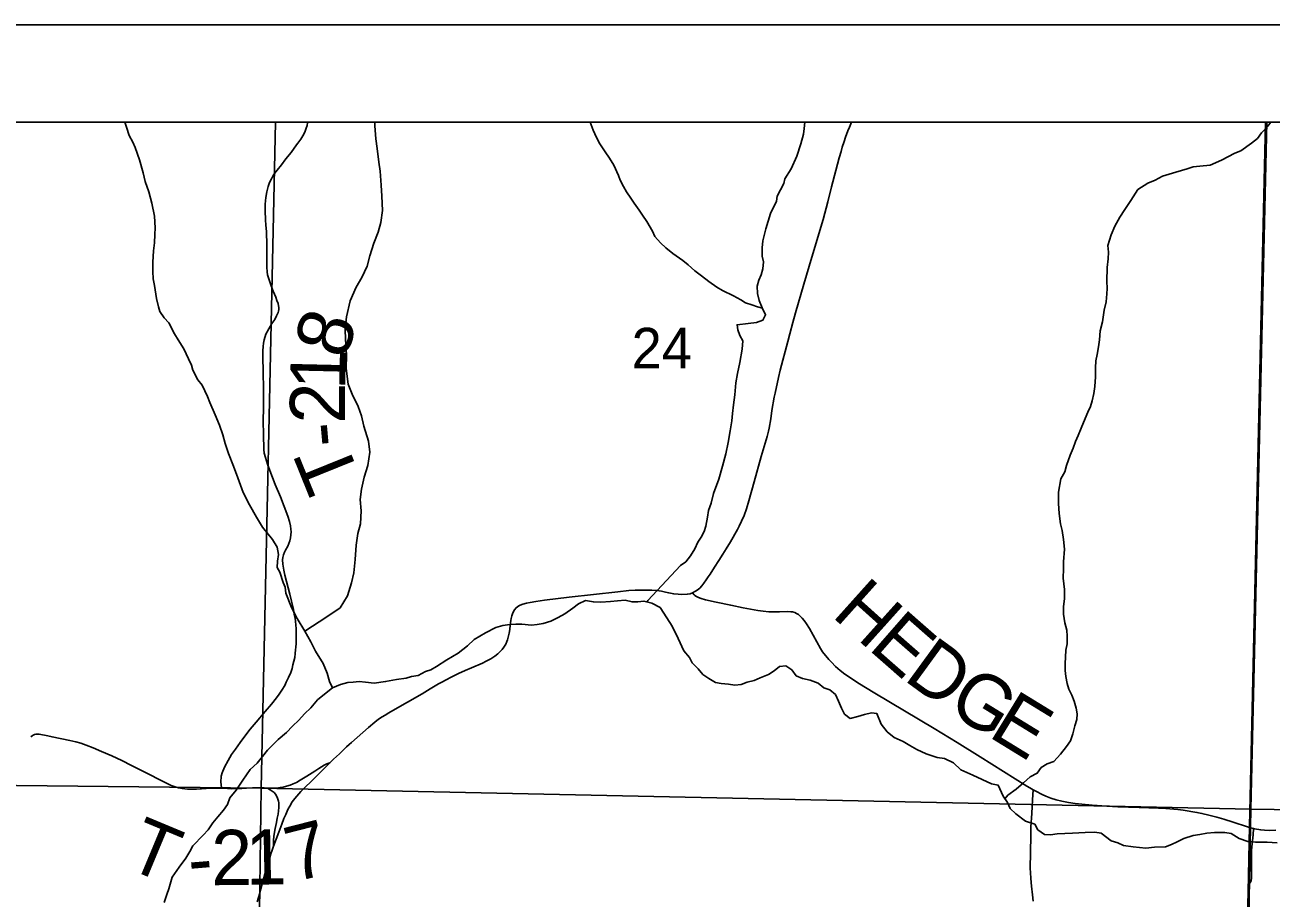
# Model space of a CAD drawing. Extents: x 0 to 34, y 0 to 22.
# Drawn here: x 20.014 to 21.298, y 19.601 to 20.5 of the extents above; entities that cross this region are included whole.
import ezdxf

# ---------------------------------------------------------------- set-up
doc = ezdxf.new("R2010")
doc.units = 0
for name, color, linetype in [('GM_X_Corporation', 7, 'Continuous'), ('GM_X_County_Road', 7, 'Continuous'), ('GM_X_Minor_River', 7, 'Continuous'), ('GM_X_Section_Text', 7, 'Continuous'), ('GM_X_Township_Road', 7, 'Continuous'), ('GM_X_Township_Road_Text', 7, 'Continuous'), ('SH_Data', 7, 'Continuous')]:
    doc.layers.add(name, color=color, linetype=linetype)

msp = doc.modelspace()

# ---------------------------------------------------------------- linework, layer by layer
at = {"layer": 'GM_X_Corporation'}
for points in [[(21.2921, 20.4), (18.6, 20.4), (18.6, 19.2331), (18.9898, 19.2261), (20.065, 19.208), (20.254, 19.2058), (20.8916, 19.1966), (21.2652, 19.1913), (21.273, 19.5535), (21.2742, 19.6071), (21.2757, 19.6748)], [(20.2723, 20.4), (19.267, 20.4), (19.2491, 19.7249), (20.2574, 19.7138)], [(21.2934, 20.4), (20.2723, 20.4), (20.2574, 19.7138), (21.2769, 19.6922)], [(25.4, 19.0068), (25.4, 20.4), (21.2921, 20.4), (21.2757, 19.6748), (21.2742, 19.6071), (21.273, 19.5535), (21.2652, 19.1913), (21.5297, 19.1865), (21.7744, 19.1817), (21.8956, 19.1793), (22.6423, 19.1645), (23.3329, 19.1508), (23.5499, 19.1465), (23.786, 19.1434), (24.169, 19.1418), (24.3186, 19.1409), (24.3186, 19.0261), (24.5766, 19.0222)], [(22.3096, 20.4), (21.2934, 20.4), (21.2769, 19.6922), (22.2928, 19.6778)], [(19.2491, 19.7249), (20.2574, 19.7138), (20.2437, 18.6978), (19.241, 18.7106), (19.2491, 19.7204)], [(21.2769, 19.6922), (21.2582, 18.6819), (20.2437, 18.6978), (20.2574, 19.7138)], [(22.2928, 19.6778), (22.2749, 18.6656), (21.2582, 18.6819), (21.2769, 19.6922)]]:
    msp.add_lwpolyline(points, close=True, dxfattribs=at)
at = {"layer": 'GM_X_County_Road'}
for points in [[(20.2997, 19.7119), (20.3028, 19.715), (20.3088, 19.721), (20.3185, 19.7304), (20.3252, 19.7371), (20.3283, 19.7401), (20.3321, 19.744), (20.338, 19.7494), (20.3453, 19.7565), (20.348, 19.7589), (20.3505, 19.7611), (20.368, 19.7763), (20.3744, 19.7818), (20.3784, 19.7849), (20.3821, 19.7874), (20.3851, 19.7893), (20.3891, 19.7916), (20.393, 19.7939), (20.4232, 19.8112), (20.4316, 19.8162), (20.4402, 19.8213), (20.4443, 19.8235), (20.4474, 19.8252), (20.454, 19.8286), (20.4607, 19.8319), (20.4676, 19.835), (20.4741, 19.8378), (20.4855, 19.8428), (20.4894, 19.8448), (20.4939, 19.8473), (20.4981, 19.85), (20.5014, 19.8524), (20.5038, 19.8546), (20.5059, 19.8568), (20.5076, 19.8591), (20.5094, 19.8621), (20.5107, 19.8649), (20.5114, 19.8667), (20.5121, 19.8696), (20.5129, 19.8736), (20.5135, 19.8773), (20.5141, 19.882), (20.5147, 19.8867), (20.515, 19.8886), (20.5156, 19.8913), (20.5163, 19.8935), (20.517, 19.8953), (20.5183, 19.8976), (20.52, 19.8997), (20.5215, 19.9008), (20.5229, 19.9018), (20.5244, 19.9025), (20.5272, 19.9036), (20.5309, 19.9046), (20.5346, 19.9053), (20.5404, 19.9062), (20.5494, 19.9075), (20.5747, 19.9107), (20.6248, 19.9163), (20.6362, 19.9174), (20.6427, 19.9178), (20.6493, 19.918), (20.6599, 19.9179), (20.6652, 19.9174), (20.6699, 19.9167), (20.6741, 19.9158), (20.6773, 19.9151), (20.6825, 19.9141), (20.6871, 19.9136), (20.6908, 19.9133), (20.6965, 19.9136), (20.6994, 19.9142), (20.7019, 19.9152), (20.7042, 19.9164), (20.7057, 19.9173), (20.7079, 19.9188), (20.7095, 19.9201), (20.7115, 19.9224), (20.7136, 19.925), (20.7159, 19.9284), (20.718, 19.9316), (20.7199, 19.9344), (20.7245, 19.9415), (20.729, 19.9484), (20.7331, 19.9548), (20.7365, 19.9603), (20.741, 19.9676), (20.7482, 19.9803), (20.75, 19.9839), (20.7524, 19.989), (20.7549, 19.9949), (20.7573, 20.0017), (20.7598, 20.01), (20.7652, 20.0296), (20.7727, 20.0555), (20.7767, 20.0693), (20.7787, 20.076), (20.7802, 20.0818), (20.7809, 20.0848), (20.7825, 20.0944), (20.7837, 20.103), (20.7861, 20.1167), (20.7869, 20.1208), (20.7904, 20.1368), (20.7922, 20.1444), (20.7999, 20.1741), (20.8021, 20.1818), (20.8052, 20.1934), (20.808, 20.2035), (20.8165, 20.233), (20.822, 20.2516), (20.8321, 20.2847), (20.8363, 20.2997), (20.8412, 20.3177), (20.8452, 20.3332), (20.8496, 20.35), (20.8531, 20.363), (20.8549, 20.3697), (20.8562, 20.374), (20.8581, 20.38), (20.8596, 20.3845), (20.862, 20.3911), (20.8635, 20.3947), (20.8656, 20.4)], [(20.2533, 19.5969), (20.2548, 19.6015), (20.256, 19.606), (20.2572, 19.6104), (20.2596, 19.6193), (20.2611, 19.6253), (20.2625, 19.6302), (20.2638, 19.6351), (20.2663, 19.6426), (20.2675, 19.6464), (20.2689, 19.6501), (20.2703, 19.6541), (20.2757, 19.6685), (20.2788, 19.677), (20.2809, 19.6826), (20.2828, 19.687), (20.2844, 19.6904), (20.2854, 19.6926), (20.2869, 19.6956), (20.2895, 19.7), (20.2922, 19.7032), (20.2982, 19.7104), (20.2997, 19.7119)]]:
    msp.add_lwpolyline(points, dxfattribs=at)
at = {"layer": 'GM_X_Minor_River'}
for points in [[(20.3308, 19.8173), (20.328, 19.8237), (20.3253, 19.8325), (20.3213, 19.8423), (20.3136, 19.8551), (20.3085, 19.8646), (20.3023, 19.8755), (20.2945, 19.8887), (20.2887, 19.9), (20.2828, 19.9148), (20.2823, 19.9209), (20.28, 19.9258), (20.2768, 19.9364), (20.2741, 19.9413), (20.2744, 19.9478), (20.2754, 19.9547), (20.2741, 19.9623), (20.2691, 19.9702), (20.2587, 19.9826), (20.2525, 19.9931), (20.2455, 20.0056), (20.2389, 20.0184), (20.2333, 20.0336), (20.229, 20.0457), (20.2239, 20.0586), (20.2203, 20.0688), (20.2179, 20.0779), (20.2144, 20.0877), (20.2101, 20.0983), (20.2046, 20.1112), (20.2022, 20.1172), (20.1967, 20.129), (20.1921, 20.1346), (20.1871, 20.1444), (20.1858, 20.1497), (20.1827, 20.1562), (20.1777, 20.1664), (20.1718, 20.1758), (20.1683, 20.1818), (20.1625, 20.1932), (20.1575, 20.1984), (20.1532, 20.2048), (20.1517, 20.2097), (20.1496, 20.2181), (20.1475, 20.2318), (20.1463, 20.2386), (20.1458, 20.2462), (20.1457, 20.2557), (20.1466, 20.2675), (20.1477, 20.2755), (20.1479, 20.2843), (20.1482, 20.2911), (20.1476, 20.3029), (20.1448, 20.3166), (20.1416, 20.328), (20.138, 20.3389), (20.136, 20.3477), (20.132, 20.3609), (20.1277, 20.3738), (20.1253, 20.3791), (20.1214, 20.3863), (20.1187, 20.3946), (20.117, 20.4)], [(20.3023, 19.8755), (20.3251, 19.8905), (20.3388, 19.8996), (20.3464, 19.9122), (20.3506, 19.9255), (20.3529, 19.9357), (20.3544, 19.9494), (20.3555, 19.9642), (20.3571, 19.9764), (20.3597, 19.9862), (20.3605, 19.9995), (20.3593, 20.0113), (20.3608, 20.0219), (20.3635, 20.0341), (20.3673, 20.0462), (20.3695, 20.0599), (20.368, 20.0713), (20.3634, 20.0869), (20.3607, 20.0975), (20.3573, 20.107), (20.3512, 20.1199), (20.347, 20.1302), (20.345, 20.1461), (20.3454, 20.1602), (20.3443, 20.1765), (20.3439, 20.1864), (20.3454, 20.1993), (20.3492, 20.216), (20.3552, 20.23), (20.361, 20.2399), (20.3667, 20.2517), (20.3693, 20.2623), (20.3735, 20.2752), (20.3781, 20.2866), (20.3807, 20.2965), (20.3826, 20.309), (20.3818, 20.3238), (20.3811, 20.3349), (20.3799, 20.3493), (20.3787, 20.3588), (20.3768, 20.3728), (20.3757, 20.3827), (20.3745, 20.396), (20.3744, 20.4)], [(20.5965, 20.4), (20.5995, 20.3915), (20.603, 20.3839), (20.6065, 20.3775), (20.612, 20.3692), (20.6162, 20.3628), (20.6209, 20.3557), (20.6256, 20.3451), (20.6272, 20.3401), (20.6307, 20.3337), (20.6338, 20.3281), (20.6384, 20.3217), (20.6419, 20.3164), (20.6469, 20.3092), (20.6504, 20.304), (20.6547, 20.2975), (20.6605, 20.2877), (20.6632, 20.2821), (20.669, 20.2757), (20.6744, 20.2704), (20.6816, 20.2645), (20.692, 20.2574), (20.6973, 20.2529), (20.7042, 20.2469), (20.7111, 20.2417), (20.7188, 20.2357), (20.7268, 20.2301), (20.7326, 20.2264), (20.744, 20.2209), (20.7516, 20.2168), (20.7566, 20.2138), (20.7631, 20.2116), (20.7688, 20.2098), (20.7739, 20.2083)], [(20.6551, 19.9057), (20.6557, 19.9072), (20.6894, 19.9433), (20.695, 19.9472), (20.6998, 19.9534), (20.7043, 19.9603), (20.7072, 19.9672), (20.7109, 19.9726), (20.7138, 19.9783), (20.7157, 19.9837), (20.7174, 19.9929), (20.7184, 20.0001), (20.721, 20.0074), (20.7235, 20.0173), (20.729, 20.0322), (20.7329, 20.0456), (20.7361, 20.0582), (20.7386, 20.0701), (20.7407, 20.0819), (20.7425, 20.0922), (20.7431, 20.0998), (20.7441, 20.1086), (20.7455, 20.1189), (20.7464, 20.1315), (20.7482, 20.141), (20.7507, 20.1525), (20.7531, 20.1662), (20.7538, 20.1746), (20.7506, 20.1802), (20.7487, 20.1859), (20.7478, 20.1912), (20.7592, 20.1926), (20.7679, 20.1934), (20.7743, 20.1958), (20.7772, 20.2016), (20.7737, 20.2088), (20.7706, 20.2163), (20.7689, 20.2235), (20.7685, 20.2311), (20.7703, 20.2373), (20.7725, 20.2426), (20.7743, 20.2487), (20.7749, 20.256), (20.7737, 20.2617), (20.7736, 20.2704), (20.7742, 20.2777), (20.7774, 20.2899), (20.7821, 20.3059), (20.7884, 20.3186), (20.7891, 20.3236), (20.7961, 20.3366), (20.7968, 20.3416), (20.8034, 20.3519), (20.8093, 20.365), (20.8136, 20.3776), (20.8161, 20.3875), (20.8168, 20.3932), (20.8175, 20.3997), (20.8175, 20.4)], [(21.0236, 19.7031), (21.0268, 19.7068), (21.0354, 19.713), (21.0428, 19.7196), (21.0496, 19.7258), (21.0571, 19.7293), (21.0612, 19.7351), (21.0672, 19.739), (21.074, 19.7414), (21.081, 19.7491), (21.087, 19.7568), (21.0911, 19.7626), (21.0936, 19.7698), (21.0958, 19.7782), (21.0979, 19.7848), (21.0982, 19.7905), (21.097, 19.7965), (21.095, 19.8037), (21.0926, 19.8098), (21.0895, 19.8158), (21.0879, 19.8219), (21.0863, 19.8291), (21.0858, 19.8352), (21.0857, 19.8424), (21.086, 19.8489), (21.0863, 19.8561), (21.0877, 19.8626), (21.088, 19.8706), (21.0875, 19.8767), (21.0855, 19.8843), (21.0839, 19.893), (21.0841, 19.901), (21.0851, 19.909), (21.085, 19.9185), (21.0837, 19.9303), (21.0839, 19.9398), (21.0842, 19.9471), (21.0851, 19.96), (21.0839, 19.9699), (21.0826, 19.9794), (21.081, 19.9862), (21.0797, 19.9968), (21.0788, 20.0071), (21.079, 20.0189), (21.0814, 20.0327), (21.0855, 20.0396), (21.0873, 20.0464), (21.0909, 20.0568), (21.0939, 20.0641), (21.0964, 20.0709), (21.099, 20.0771), (21.1023, 20.0847), (21.1063, 20.0947), (21.1092, 20.1012), (21.1118, 20.107), (21.1136, 20.1127), (21.1154, 20.1203), (21.1164, 20.1276), (21.117, 20.1375), (21.1169, 20.147), (21.1175, 20.1539), (21.1186, 20.1607), (21.12, 20.1684), (21.121, 20.1756), (21.122, 20.1851), (21.1241, 20.1943), (21.1259, 20.2061), (21.128, 20.2149), (21.1286, 20.2229), (21.1289, 20.2286), (21.1288, 20.2362), (21.129, 20.2503), (21.13, 20.2591), (21.1303, 20.2659), (21.1298, 20.2728), (21.133, 20.2839), (21.1371, 20.2927), (21.1422, 20.3019), (21.1471, 20.31), (21.1534, 20.3192), (21.1608, 20.3304), (21.1709, 20.337), (21.1784, 20.3401), (21.1859, 20.3441), (21.1999, 20.3485), (21.2116, 20.3517), (21.2176, 20.3537), (21.2244, 20.3545), (21.235, 20.3555), (21.247, 20.3606), (21.2606, 20.368), (21.2666, 20.3704), (21.2778, 20.3782), (21.2838, 20.3829), (21.2879, 20.389), (21.2946, 20.3956), (21.2976, 20.4)], [(20.2027, 19.6712), (20.2075, 19.6781), (20.2127, 19.6846), (20.2187, 19.6912), (20.2227, 19.697), (20.2253, 19.7039), (20.2316, 19.7119), (20.2387, 19.7223), (20.2461, 19.7331), (20.2532, 19.7397), (20.2587, 19.7466), (20.2639, 19.7531), (20.2751, 19.764), (20.2834, 19.7713), (20.2897, 19.7779), (20.2961, 19.7841), (20.302, 19.7906), (20.3087, 19.7968), (20.3154, 19.8049), (20.3244, 19.8123), (20.3308, 19.8173), (20.3391, 19.8209), (20.3466, 19.8229), (20.3523, 19.8233), (20.3583, 19.8238), (20.3648, 19.8232), (20.3739, 19.8221), (20.3856, 19.8238), (20.3969, 19.8259), (20.4067, 19.8272), (20.4124, 19.8288), (20.4192, 19.8301), (20.4267, 19.834), (20.4323, 19.836), (20.438, 19.8391), (20.4489, 19.8461), (20.4605, 19.8531), (20.4702, 19.8605), (20.4769, 19.8671), (20.4826, 19.8706), (20.4886, 19.8741), (20.4991, 19.8796), (20.5066, 19.8816), (20.5138, 19.8825), (20.5199, 19.8829), (20.5259, 19.8827), (20.5358, 19.882), (20.5418, 19.8825), (20.5479, 19.8834), (20.5558, 19.8858), (20.5633, 19.8897), (20.5704, 19.8936), (20.5787, 19.8994), (20.5843, 19.9037), (20.5915, 19.9072), (20.5998, 19.9058), (20.6074, 19.9056), (20.6172, 19.9061), (20.6244, 19.907), (20.6323, 19.9075), (20.6396, 19.9057), (20.6456, 19.9058), (20.6517, 19.9066), (20.66, 19.9045), (20.6684, 19.9), (20.6754, 19.8895), (20.6808, 19.8808), (20.6871, 19.868), (20.6929, 19.8555), (20.6987, 19.8487), (20.7014, 19.843), (20.7076, 19.8367), (20.7126, 19.831), (20.7187, 19.8269), (20.7256, 19.8229), (20.7313, 19.8218), (20.7389, 19.8212), (20.7453, 19.8201), (20.7521, 19.8206), (20.7581, 19.823), (20.7653, 19.825), (20.7717, 19.8277), (20.78, 19.8309), (20.786, 19.8348), (20.7916, 19.8391), (20.798, 19.8399), (20.8041, 19.8358), (20.8088, 19.8298), (20.8152, 19.8269), (20.8232, 19.8251), (20.8312, 19.8222), (20.8373, 19.8173), (20.8434, 19.8151), (20.8492, 19.8103), (20.8523, 19.8035), (20.8554, 19.7963), (20.8586, 19.7902), (20.8643, 19.7858), (20.8722, 19.7878), (20.879, 19.7898), (20.8862, 19.7914)], [(20.8862, 19.7914), (20.8919, 19.7907), (20.8962, 19.7798), (20.9024, 19.7719), (20.9096, 19.7663), (20.9188, 19.7619), (20.9257, 19.7578), (20.9329, 19.7537), (20.9425, 19.7493), (20.9539, 19.7456), (20.9615, 19.7446), (20.9706, 19.7402), (20.9783, 19.7327), (20.9905, 19.7272), (21.0099, 19.7183), (21.0168, 19.7169), (21.0219, 19.7056), (21.0265, 19.6992), (21.0292, 19.6931), (21.035, 19.6875), (21.0449, 19.68), (21.0545, 19.6768), (21.0576, 19.6711), (21.0645, 19.6663), (21.0705, 19.666), (21.0777, 19.6668), (21.0932, 19.6675), (21.1064, 19.6684), (21.1163, 19.6686), (21.1227, 19.6675), (21.1331, 19.6597), (21.1399, 19.6575), (21.146, 19.6549), (21.1559, 19.6536), (21.1688, 19.6522), (21.1779, 19.6531), (21.1892, 19.6537), (21.1952, 19.6561), (21.2012, 19.6588), (21.208, 19.662), (21.2178, 19.6652), (21.2246, 19.6664), (21.2318, 19.6677), (21.2397, 19.6682), (21.2503, 19.6683), (21.2568, 19.6673), (21.2652, 19.6621), (21.2739, 19.6592), (21.2819, 19.6585), (21.2876, 19.6582), (21.294, 19.6583), (21.3042, 19.6577)], [(20.1576, 19.5963), (20.1601, 19.6043), (20.1623, 19.6104), (20.1659, 19.6223), (20.173, 19.6327), (20.18, 19.6419), (20.1841, 19.6488), (20.187, 19.6546), (20.1978, 19.6654), (20.2027, 19.6712)]]:
    msp.add_lwpolyline(points, dxfattribs=at)
at = {"layer": 'GM_X_Township_Road'}
for points in [[(20.2167, 19.7138), (20.2161, 19.7177), (20.2159, 19.7202), (20.2163, 19.7263), (20.2174, 19.7298), (20.2198, 19.7356), (20.2234, 19.7425), (20.227, 19.7485), (20.2309, 19.7542), (20.2357, 19.7609), (20.2395, 19.7661), (20.2462, 19.7747), (20.2522, 19.7821), (20.2616, 19.7928), (20.2681, 19.8004), (20.2732, 19.807), (20.276, 19.8109), (20.2787, 19.815), (20.2817, 19.8197), (20.2833, 19.823), (20.2857, 19.8281), (20.2879, 19.8332), (20.2893, 19.8371), (20.2902, 19.8409), (20.2912, 19.8449), (20.292, 19.8486), (20.2925, 19.8527), (20.2929, 19.8565), (20.2931, 19.8591), (20.2935, 19.863), (20.2936, 19.8682), (20.2935, 19.8785), (20.2932, 19.882), (20.2928, 19.8859), (20.2924, 19.8888), (20.2915, 19.8933), (20.2906, 19.8981), (20.287, 19.9136), (20.2817, 19.9335), (20.2807, 19.9386), (20.2799, 19.9446), (20.2795, 19.9491), (20.2798, 19.9515), (20.2803, 19.9543), (20.2814, 19.9569), (20.2825, 19.9591), (20.2848, 19.9631), (20.286, 19.966), (20.2871, 19.9688), (20.2876, 19.9719), (20.288, 19.9747), (20.2882, 19.978), (20.288, 19.9807), (20.2876, 19.9842), (20.2868, 19.9885), (20.2849, 19.9942), (20.2774, 20.0139), (20.2718, 20.0266), (20.2663, 20.0411), (20.2639, 20.0477), (20.2618, 20.0545), (20.2607, 20.0589), (20.2603, 20.0626), (20.2601, 20.0679), (20.2598, 20.0729), (20.2597, 20.0796), (20.2595, 20.0904), (20.2597, 20.1074), (20.2599, 20.1253), (20.2595, 20.1423), (20.2591, 20.1585), (20.2593, 20.1644), (20.2594, 20.1688), (20.2599, 20.1721), (20.2607, 20.1757), (20.2624, 20.1815), (20.2652, 20.1871), (20.2685, 20.1924), (20.2714, 20.1966), (20.2734, 20.2004), (20.2751, 20.2038), (20.2754, 20.2052), (20.2756, 20.2071), (20.2755, 20.2089), (20.2753, 20.2106), (20.2749, 20.2131), (20.2737, 20.2161), (20.2724, 20.2196), (20.2712, 20.2226), (20.2699, 20.2258), (20.2676, 20.2312), (20.2659, 20.2364), (20.264, 20.2426), (20.2637, 20.2456), (20.2633, 20.2506), (20.2634, 20.2553), (20.2632, 20.2733), (20.2628, 20.2871), (20.2623, 20.2937), (20.2618, 20.2994), (20.2616, 20.3084), (20.2617, 20.3154), (20.2622, 20.3222), (20.2633, 20.3282), (20.2648, 20.3337), (20.2661, 20.3378), (20.268, 20.3414), (20.2703, 20.3455), (20.2739, 20.3505), (20.2783, 20.356), (20.2828, 20.3622), (20.2882, 20.3687), (20.294, 20.3765), (20.2954, 20.3783), (20.2982, 20.3825), (20.3013, 20.3875), (20.3029, 20.3907), (20.3039, 20.3936), (20.3047, 20.3964), (20.3052, 20.3991), (20.3054, 20.4)], [(20.7019, 19.9152), (20.7035, 19.9132), (20.7044, 19.9123), (20.7061, 19.9113), (20.708, 19.9104), (20.7107, 19.9094), (20.7153, 19.9079), (20.7261, 19.9056), (20.7413, 19.9024), (20.7541, 19.8998), (20.7654, 19.8976), (20.769, 19.897), (20.7746, 19.8962), (20.7805, 19.8957), (20.7858, 19.8955), (20.7913, 19.8956), (20.7996, 19.8959), (20.8031, 19.8957), (20.805, 19.8954), (20.8073, 19.8949), (20.8091, 19.894), (20.8111, 19.8927), (20.8149, 19.8889), (20.8169, 19.8866), (20.8193, 19.8832), (20.8223, 19.8784), (20.8337, 19.8579), (20.8358, 19.8544), (20.8423, 19.8464), (20.8449, 19.8436), (20.8492, 19.8394), (20.8539, 19.8353), (20.8588, 19.8314), (20.8625, 19.8288), (20.8721, 19.8226), (20.8898, 19.8118), (20.9509, 19.7753), (20.9746, 19.7609), (20.9983, 19.7463), (21.0464, 19.7161), (21.0495, 19.7142), (21.0527, 19.7123), (21.0554, 19.7108), (21.0622, 19.7074), (21.0659, 19.7057), (21.0711, 19.7037), (21.0764, 19.702), (21.0825, 19.7005), (21.0893, 19.6992), (21.0961, 19.6982), (21.1028, 19.6974), (21.1136, 19.6965), (21.1286, 19.6956), (21.14, 19.6949), (21.162, 19.6941), (21.1819, 19.6934), (21.1896, 19.693), (21.2019, 19.692), (21.2075, 19.6912), (21.2215, 19.689), (21.2266, 19.688), (21.2337, 19.6863), (21.2421, 19.6841), (21.2492, 19.682), (21.2587, 19.6788), (21.2735, 19.674), (21.2763, 19.6732), (21.2784, 19.6727), (21.2799, 19.6724)], [(20.0203, 19.767), (20.0215, 19.768), (20.0226, 19.7687), (20.0239, 19.7693), (20.0254, 19.7696), (20.0271, 19.7697), (20.0288, 19.7695), (20.0377, 19.7678), (20.042, 19.7668), (20.0604, 19.763), (20.0665, 19.7616), (20.0717, 19.7602), (20.0773, 19.7582), (20.0843, 19.7556), (20.0931, 19.7519), (20.1037, 19.7471), (20.114, 19.7423), (20.1237, 19.7373), (20.1347, 19.7317), (20.16, 19.719), (20.1648, 19.7167), (20.1689, 19.7153), (20.1723, 19.7143), (20.1759, 19.7137), (20.1789, 19.7133), (20.1815, 19.7131), (20.1867, 19.713), (20.1909, 19.713), (20.2059, 19.7138), (20.2085, 19.7139), (20.2167, 19.7138), (20.2228, 19.7135), (20.2272, 19.7134), (20.2333, 19.7135), (20.2374, 19.7137), (20.2425, 19.7141), (20.2484, 19.7144), (20.2605, 19.7143), (20.2641, 19.7141), (20.2678, 19.7139), (20.2733, 19.714), (20.2769, 19.7145), (20.2801, 19.715), (20.2834, 19.7159), (20.2872, 19.7172), (20.2905, 19.7184), (20.294, 19.7199), (20.2977, 19.7221), (20.3045, 19.7263), (20.3127, 19.7314), (20.317, 19.7342), (20.3225, 19.7375), (20.3252, 19.7389), (20.3283, 19.7401)], [(20.2703, 19.6541), (20.2701, 19.6562), (20.2702, 19.6602), (20.2706, 19.6646), (20.272, 19.6724), (20.2733, 19.6786), (20.2741, 19.683), (20.2749, 19.6873), (20.2754, 19.6906), (20.2757, 19.694), (20.2755, 19.6989), (20.2753, 19.7007), (20.2744, 19.7035), (20.273, 19.7066), (20.2721, 19.7078), (20.2707, 19.7096), (20.2689, 19.711), (20.2669, 19.7123), (20.2641, 19.7141)], [(21.0527, 19.5975), (21.052, 19.6042), (21.0511, 19.613), (21.0503, 19.6211), (21.0499, 19.627), (21.0496, 19.6314), (21.0503, 19.665), (21.0505, 19.674), (21.0513, 19.688), (21.0521, 19.702), (21.0527, 19.7123)], [(21.2755, 19.6153), (21.2768, 19.6172), (21.2774, 19.619), (21.2776, 19.6214), (21.2778, 19.6241), (21.2777, 19.6402), (21.2778, 19.6497), (21.278, 19.6536), (21.2793, 19.666), (21.2799, 19.6724)], [(21.2799, 19.6724), (21.281, 19.6721), (21.2873, 19.671), (21.2911, 19.6706), (21.296, 19.6704), (21.3027, 19.6706)]]:
    msp.add_lwpolyline(points, dxfattribs=at)
at = {"layer": 'SH_Data'}
for points in [[(18.5, 20.5), (25.5, 20.5), (25.5, 13.5), (18.5, 13.5)], [(18.6, 20.4), (25.4, 20.4), (25.4, 13.6), (18.6, 13.6)]]:
    msp.add_lwpolyline(points, close=True, dxfattribs=at)

# ---------------------------------------------------------------- texts
at = {"layer": 'GM_X_Section_Text'}
msp.add_text('24', height=0.04186, rotation=0, dxfattribs=at).set_placement((20.6391, 20.1462))
at = {"layer": 'GM_X_Township_Road_Text'}
for s, rotation, p in [('8', 71.9225, (20.344, 20.1542)), ('1', 88.678, (20.3439, 20.1238)), ('2', 89.7378, (20.3438, 20.0893)), ('-', 95.1211, (20.3458, 20.0677)), ('T', 111.9909, (20.3606, 20.0327)), ('H', 318.1002, (20.8441, 19.8916)), ('E', 318.7821, (20.8818, 19.8577)), ('D', 323.8984, (20.9181, 19.8262)), ('G', 328.4484, (20.9626, 19.794)), ('E', 328.4913, (21.0053, 19.7679)), ('T', 337.39, (20.1159, 19.633)), ('7', 14.3255, (20.291, 19.6169)), ('2', 0.4944, (20.2062, 19.614)), ('1', 1.1092, (20.2419, 19.6143)), ('-', 4.704, (20.184, 19.6121))]:
    msp.add_text(s, height=0.0568, rotation=rotation, dxfattribs=at).set_placement(p)

doc.saveas('drawing.dxf')
